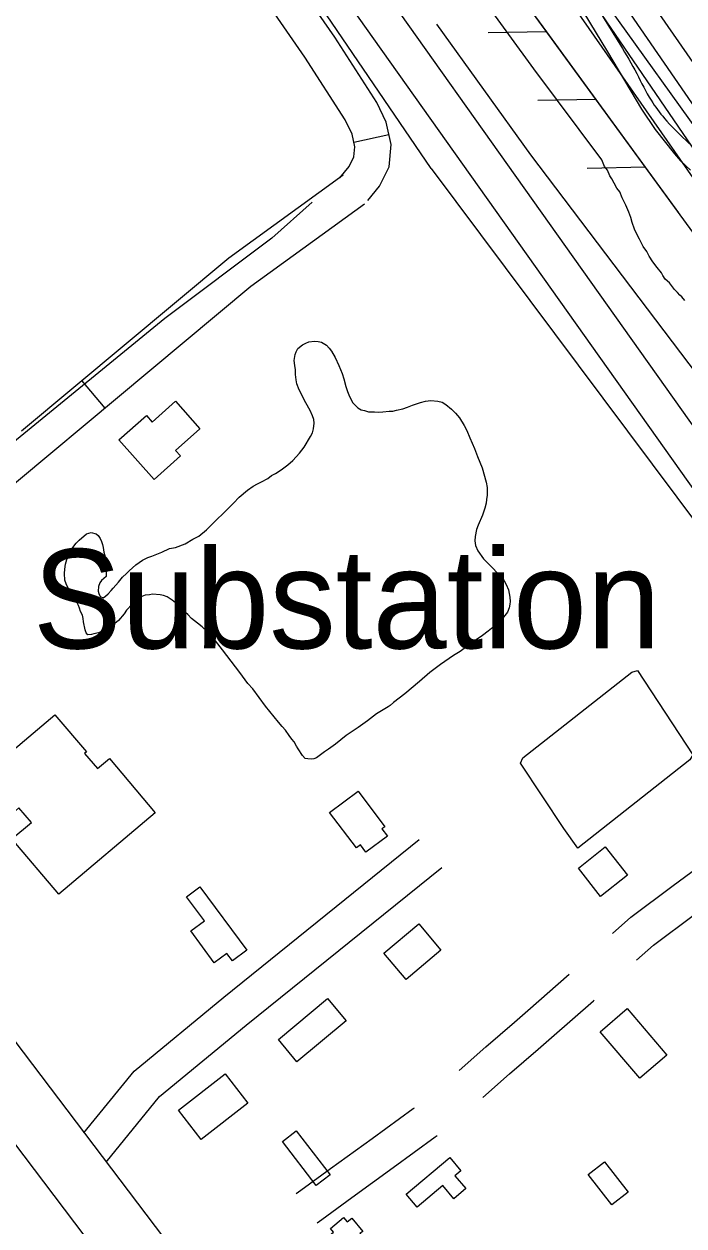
# Model space of a CAD drawing. Extents: x 3892998 to 3931244, y 278583 to 304547.
# Drawn here: x 3910038 to 3910590, y 288917 to 289921 of the extents above; entities that cross this region are included whole.
import ezdxf

# ---------------------------------------------------------------- set-up
doc = ezdxf.new("R2010")
doc.units = 0
for name, color, linetype in [('V-BLDG-OTLN', 7, 'Continuous'), ('V-LEVE-TOET', 7, 'Continuous'), ('V-RIVR-EDGE', 7, 'Continuous'), ('V-ROAD-CNTR', 7, 'Continuous'), ('V-RRAP-FSHR', 7, 'Continuous'), ('V-RRAP-RVMT', 7, 'Continuous'), ('V-SITE-OTLN', 7, 'Continuous'), ('V-SITE-OTLN-IDEN', 7, 'Continuous'), ('V-SITE-VEGE', 7, 'Continuous'), ('V-SURV-LINE', 7, 'Continuous'), ('V-TOPO-DPTH', 7, 'Continuous'), ('V-TOPO-MINR', 7, 'Continuous'), ('V-TOPO-SHOR', 7, 'Continuous'), ('V-TOPO-WATR', 7, 'Continuous')]:
    doc.layers.add(name, color=color, linetype=linetype)

msp = doc.modelspace()

# ---------------------------------------------------------------- linework, layer by layer
at = {"layer": 'V-BLDG-OTLN'}
for points in [[(3910146.9, 289540.7), (3910117.6, 289573.6), (3910140.5, 289594.1), (3910145.3, 289588.6), (3910164.8, 289605.9), (3910185.3, 289582.9), (3910164.9, 289564.8), (3910168.9, 289560.3)], [(3910147.9, 289262.1), (3910067.4, 289194), (3910028.2, 289240.3), (3910044.5, 289254.1), (3910034.1, 289266.3), (3910030.8, 289263.4), (3910017.8, 289278.8), (3910020.5, 289281.1), (3910007.6, 289296.3), (3910064, 289344), (3910090.4, 289312.9), (3910088.9, 289311.7), (3910099.6, 289299), (3910109.6, 289307.4)], [(3910317.3, 289280.1), (3910339.6, 289250.4), (3910337.3, 289248.7), (3910341.9, 289242.7), (3910323.9, 289229.1), (3910319.3, 289235.2), (3910315.9, 289232.7), (3910293.6, 289262.3)], [(3910542.5, 289209.9), (3910520, 289192.3), (3910501.4, 289215.9), (3910523.9, 289233.6)], [(3910185.3, 289200.2), (3910224.3, 289147.2), (3910212.4, 289138.4), (3910207.8, 289144.6), (3910197.2, 289136.8), (3910177.6, 289163.4), (3910189, 289171.8), (3910174.1, 289192)], [(3910386.6, 289147.4), (3910357.5, 289122.8), (3910339, 289144.8), (3910368.1, 289169.4)], [(3910307.3, 289088.4), (3910266.3, 289054.1), (3910250.8, 289072.7), (3910291.9, 289106.9)], [(3910542.1, 289098.6), (3910575.3, 289059.7), (3910552.7, 289040.4), (3910519.5, 289079.2)], [(3910225.3, 289019.4), (3910186.4, 288989.1), (3910167.3, 289013.6), (3910206.2, 289043.9)], [(3910265.7, 288996.4), (3910293.9, 288959.5), (3910282.3, 288950.7), (3910254.1, 288987.6)], [(3910357.4, 288943.4), (3910394, 288974), (3910403.2, 288963), (3910398.3, 288958.9), (3910407.4, 288948.1), (3910397.3, 288939.7), (3910388.2, 288950.6), (3910366.6, 288932.5)], [(3910523.2, 288970.6), (3910542.9, 288945.2), (3910529.2, 288934.6), (3910509.5, 288959.9)], [(3910267.8, 288887.4), (3910296.8, 288911.7), (3910294.2, 288914.7), (3910305.2, 288923.9), (3910308.3, 288920.3), (3910312, 288923.4), (3910321.2, 288912.4), (3910318.9, 288910.5), (3910324, 288904.4), (3910308.3, 288891.2), (3910304.4, 288895.8), (3910278.7, 288874.3)]]:
    msp.add_lwpolyline(points, close=True, dxfattribs=at)
at = {"layer": 'V-LEVE-TOET'}
for points in [[(3910378.5, 289800.4), (3910286.7, 289934.9)], [(3910382.9, 289921.1), (3910461.3, 289811.8)], [(3910461.3, 289811.8), (3910628.4, 289591.3), (3910849.1, 289281.4), (3911091.8, 288969.6), (3911307.9, 288682.5), (3911517.2, 288398.5), (3911743.1, 288106.7), (3911912.1, 287856.3), (3912092.1, 287562.1), (3912212.1, 287362), (3912215.6, 287348.2), (3912217.6, 287327.5), (3912216.8, 287307.9), (3912213.6, 287294.6), (3912212.9, 287280.1), (3912210.5, 287267.1), (3912206.6, 287249.1), (3912208.2, 287229.1), (3912212.5, 287213.8), (3912244.7, 287037.1), (3912258.5, 286987.4), (3912297.4, 286872.3), (3912300, 286844.5)], [(3910378.5, 289800.4), (3910604.3, 289498.3), (3910825.8, 289187.7), (3910970.9, 289000.1), (3911108.1, 288812.8), (3911171.6, 288734.9), (3911181.1, 288722.3), (3911187.7, 288714.9), (3911192.8, 288707.8), (3911200.7, 288696.1), (3911205.8, 288690.6), (3911212, 288681.6), (3911221.8, 288665.5), (3911335.2, 288506.1), (3911542.6, 288236.2), (3911714.3, 288010.6), (3911862.9, 287789.6), (3911999.4, 287569.5), (3912128.4, 287357.1)]]:
    msp.add_lwpolyline(points, dxfattribs=at)
at = {"layer": 'V-RIVR-EDGE'}
msp.add_spline([(3909865.8, 290928.2), (3909862.6, 290923.1), (3909860.7, 290922.6), (3909860.7, 290920.7), (3909870.3, 290905.1), (3909881.9, 290877.9), (3909893.5, 290856.5), (3909906.1, 290843.8), (3909921.6, 290817.6), (3909937.1, 290794.7), (3909948.2, 290777.2), (3909977.7, 290734.4), (3910003.4, 290694.5), (3910040.6, 290645.9), (3910078.4, 290595.3), (3910114.2, 290544.2), (3910151.5, 290493.6), (3910182, 290444.5), (3910200.8, 290413.3), (3910226.9, 290368.6), (3910256.9, 290323.8), (3910278.7, 290289.3), (3910307.7, 290250.4), (3910325.2, 290226.5), (3910363.9, 290167.2), (3910391.4, 290124.9), (3910427.7, 290068.9), (3910449.5, 290036.8), (3910504.2, 289956.6), (3910522.1, 289926.9), (3910550.1, 289879.7), (3910562.2, 289857.4), (3910573.3, 289842.3), (3910610.6, 289806.7), (3910620.8, 289794.1), (3910623.2, 289780), (3910634.8, 289764.4), (3910664.8, 289724), (3910692.4, 289689.5), (3910710.8, 289668.1), (3910721, 289660.3), (3910770.9, 289605.3), (3910782.5, 289588.7), (3910807.7, 289548.4), (3910835.7, 289503.6), (3910862.8, 289470), (3910892.3, 289425.8), (3910920.4, 289383.5), (3910948, 289342.6), (3910968.8, 289304.7), (3911000.2, 289260.9), (3911019.6, 289231.7), (3911055.9, 289191.3), (3911085.5, 289159.7), (3911118.9, 289116.8), (3911139.2, 289091.1), (3911161, 289062.3), (3911184.2, 289025.9), (3911223.4, 288981.6), (3911281.5, 288916.4), (3911313, 288876.9), (3911328.5, 288859.4), (3911346.4, 288837.5), (3911371.6, 288801), (3911404.5, 288751.9), (3911426.7, 288715.4), (3911446.6, 288687.7), (3911479, 288646.8), (3911529.4, 288582.1), (3911550.6, 288552.9), (3911609.2, 288468.3), (3911644.5, 288421.1), (3911677, 288378.8), (3911701.2, 288348.1), (3911741.4, 288303.8), (3911770.9, 288264.9), (3911788.8, 288235.7), (3911834.3, 288164.7), (3911857.5, 288130.2), (3911884.6, 288092.7), (3911915.6, 288045.5), (3911921.9, 288035.8), (3911928.6, 288029.9), (3911972.6, 287945.8), (3911992.9, 287906.4), (3912000.6, 287887), (3912014.7, 287866.5), (3912026.8, 287848.1), (3912066.4, 287785.3), (3912084.8, 287750.8), (3912094.5, 287732.8), (3912094.9, 287726), (3912096.8, 287711.4), (3912096.3, 287704.6), (3912095.4, 287700.3), (3912088.6, 287695.9), (3912085.6, 287696.9), (3912073, 287702.3), (3912062.4, 287706.2), (3912054.1, 287706.2), (3912051.2, 287704.3), (3912049.2, 287697.9), (3912054, 287685.8), (3912068.6, 287663.9), (3912113.1, 287586.6), (3912136.7, 287540.9), (3912153.7, 287513.6), (3912163.8, 287503.9), (3912187.6, 287479.6), (3912207.4, 287453.3), (3912216.1, 287446), (3912226.8, 287436.2), (3912240.8, 287416.8), (3912253.4, 287397.8), (3912271.3, 287366.2), (3912283.9, 287341.4), (3912284.8, 287339), (3912290.2, 287338), (3912303.8, 287344.3), (3912317.4, 287350.5), (3912319.8, 287350.5), (3912322.7, 287350.5), (3912327.6, 287345.7), (3912328.5, 287338.4), (3912335.8, 287321.4), (3912348.4, 287300), (3912369.2, 287275.1), (3912380.3, 287265.4), (3912402.1, 287253.2), (3912416.7, 287243.5), (3912434.2, 287238.1), (3912456.9, 287220), (3912481.6, 287183.6), (3912501.9, 287148.1), (3912512.6, 287124.7), (3912531.4, 287085.8), (3912550.3, 287059.6), (3912569.6, 287034.3), (3912593.3, 286996.8), (3912613.7, 286968.1), (3912632, 286936.5), (3912645.1, 286912.7), (3912660.6, 286888.8), (3912675.1, 286867.4), (3912698.3, 286835.3), (3912720.1, 286784.8), (3912737, 286747.8), (3912742.3, 286740), (3912755.3, 286715.2), (3912761.6, 286696.8), (3912774.1, 286660.3), (3912779.9, 286635.5), (3912793.4, 286585.5), (3912797.2, 286569.4), (3912804, 286543.7), (3912804.4, 286532)], degree=3, dxfattribs=at)
at = {"layer": 'V-ROAD-CNTR'}
for p, q in [((3910313.8, 289822.3), (3910343.1, 289828.8)), ((3910086.4, 289623.2), (3910105.7, 289600.1))]:
    msp.add_line(p, q, dxfattribs=at)
for points in [[(3905312.5, 295227.1), (3905668.2, 294755.9), (3905995.9, 294324.8), (3906423.6, 293758.8), (3906727.8, 293356.2), (3907205.3, 292726.9), (3907628, 292163.3), (3908430.5, 291100.9), (3908883.9, 290504.6), (3909506.7, 289678.1), (3910240.4, 288708.1), (3910610.7, 288220.9)], [(3906034.2, 294352.1), (3906739.3, 293416.8), (3907556.8, 292335.4), (3908052.7, 291678.7), (3908621.7, 290930.2), (3909105, 290293.1), (3909494.8, 289778.2), (3910015.5, 289090.8), (3910630.8, 288278.7)], [(3910325.5, 289773.7), (3910335.2, 289785.7), (3910343.2, 289801.9), (3910344.9, 289820.4), (3910340.8, 289839), (3910333, 289855.6), (3910297.9, 289910.1), (3910262.3, 289961.6)], [(3910302.1, 289792.5), (3910309.8, 289802), (3910313.8, 289810.2), (3910314.6, 289818.5), (3910312.3, 289829.2), (3910306.7, 289841), (3910273, 289893.5), (3910237.8, 289944.4)], [(3910036.2, 289581.3), (3910209.5, 289725.8), (3910305, 289795.2)], [(3909819.8, 289351.7), (3909922, 289446.9), (3910227.9, 289702.2), (3910322.6, 289770.9)], [(3910088.3, 288994.7), (3910130.2, 289046.3), (3910205.1, 289108), (3910368.4, 289239.8)], [(3910530, 289161.3), (3910545.2, 289174.9), (3910580.5, 289201.3), (3910615.4, 289227.1), (3910628.3, 289236.9)], [(3910107, 288970.1), (3910151.6, 289025.1), (3910224, 289084.8), (3910387.2, 289216.4)], [(3910550, 289138.9), (3910564.2, 289151.6), (3910598.4, 289177.2), (3910633.4, 289203.1), (3910646.4, 289213)], [(3910448.1, 289087.3), (3910459.1, 289096.9), (3910493.7, 289127.2), (3910493.8, 289127.3)], [(3910467.8, 289064.7), (3910478.9, 289074.3), (3910514, 289105.1), (3910514.6, 289105.6)], [(3910401.8, 289046.7), (3910424.1, 289066.5), (3910448.1, 289087.3)], [(3910421.6, 289024.2), (3910443.9, 289043.9), (3910467.8, 289064.7)], [(3910265.6, 288943.9), (3910269.5, 288946.7), (3910294.4, 288964.8), (3910329.2, 288990), (3910363.5, 289015), (3910364.4, 289015.7)], [(3910283.3, 288919.6), (3910287.2, 288922.4), (3910312, 288940.6), (3910346.8, 288965.7), (3910381.8, 288991.3), (3910383.3, 288992.5)]]:
    msp.add_lwpolyline(points, dxfattribs=at)
at = {"layer": 'V-RRAP-FSHR'}
for p, q in [((3910475, 289914.6), (3910426.1, 289913.7)), ((3910516.2, 289858), (3910467.4, 289857.1)), ((3910557.5, 289801.5), (3910508.6, 289800.5))]:
    msp.add_line(p, q, dxfattribs=at)
for points in [[(3906808.7, 295088), (3907517.5, 294080), (3908118.6, 293281.7), (3908235.5, 293171.3), (3908399.7, 292987.4), (3908497.6, 292843.4), (3908620.8, 292699.4), (3908781.9, 292472.6), (3908840.2, 292361), (3908947.1, 292209.3), (3909156.9, 291945.8), (3909268, 291726.3), (3910057.1, 290568.3), (3910757.5, 289562.2), (3911229.4, 288921.6), (3911814.1, 288135.2), (3912099.8, 287690.4), (3912357.7, 287495.4), (3912493.3, 287323.3)], [(3911412.6, 288622.2), (3911308, 288752.8), (3911327.8, 288790.6), (3910785.8, 289488.4), (3910445.8, 289954.6), (3910129.3, 290398), (3909798.6, 290866.3), (3909546.9, 291228.9), (3909473.8, 291330.5), (3909414.7, 291394.5), (3909312.2, 291557.4), (3909036.8, 291981.1), (3908774.4, 292360.3)], [(3910475, 289914.6), (3910445.8, 289954.6), (3910433.9, 289971.3)], [(3910516.2, 289858), (3910475, 289914.6)], [(3910557.5, 289801.5), (3910516.2, 289858)], [(3910585.2, 289763.5), (3910557.5, 289801.5)]]:
    msp.add_lwpolyline(points, dxfattribs=at)
at = {"layer": 'V-RRAP-RVMT'}
msp.add_line((3910608.8, 289821.2), (3910527.1, 289935), dxfattribs=at)
at = {"layer": 'V-SITE-OTLN'}
msp.add_lwpolyline([(3910489.1, 289248.9), (3910452.9, 289303.5), (3910454.9, 289308), (3910546.1, 289379.5), (3910550.8, 289381.1), (3910597, 289310.5), (3910594.4, 289306.4), (3910500.8, 289232.5)], close=True, dxfattribs=at)
at = {"layer": 'V-SITE-VEGE'}
for points in [[(3910210.8, 290369), (3910280.2, 290265.4), (3910366.8, 290137.5), (3910460.7, 290005.1), (3910525.6, 289897.9), (3910554.1, 289850), (3910565.5, 289833.1), (3910581.6, 289812.7), (3910586.8, 289806.7)], [(3910590.3, 289690.2), (3910587.8, 289693.3), (3910586, 289694.5), (3910584.2, 289696.9), (3910581.8, 289699.3), (3910577.5, 289704.8), (3910573.8, 289707.9), (3910572, 289710.9), (3910570.8, 289713.3), (3910567.1, 289717.6), (3910563.5, 289722.5), (3910560.4, 289727.3), (3910558.6, 289731), (3910555.6, 289735.2), (3910552.5, 289741.3), (3910550.1, 289745.6), (3910548.3, 289749.8), (3910546.4, 289755.3), (3910545.2, 289759.6), (3910543.4, 289763.8), (3910541, 289769.9), (3910537.9, 289776), (3910536.1, 289780.9), (3910533.6, 289783.9), (3910531.2, 289788.2), (3910529.4, 289791.8), (3910527.6, 289794.2), (3910525.7, 289799.1), (3910523.3, 289802.2), (3910520.9, 289807.6), (3910464.2, 289883.8), (3910422.3, 289941)], [(3910586.8, 289806.7), (3910595.1, 289799.1)], [(3910241.9, 289541.5), (3910245, 289543.8), (3910248.4, 289545.6), (3910253.1, 289548.6), (3910258.6, 289552.9), (3910262.8, 289556.5), (3910268.5, 289562.6), (3910272.4, 289567.5), (3910277.6, 289576.4), (3910279.2, 289579.6), (3910280.1, 289582.9), (3910280.7, 289587.7), (3910280.3, 289590.6), (3910279.3, 289593.8), (3910277.4, 289598.1), (3910273.6, 289604.7), (3910268.1, 289615.5), (3910266.3, 289620.5), (3910265.5, 289623.8), (3910265.1, 289628.2), (3910265.1, 289632.3), (3910264.5, 289635.7), (3910264.1, 289640), (3910264.7, 289644.9), (3910265.5, 289647.3), (3910267.1, 289649.9), (3910270.8, 289653), (3910273.6, 289654.6), (3910276.2, 289655.6), (3910280.9, 289656.2), (3910284.1, 289656), (3910286.8, 289655.2), (3910291, 289652.7), (3910293.1, 289650.3), (3910295.1, 289647.7), (3910298.1, 289642.4), (3910301.4, 289635.7), (3910304, 289629), (3910305.4, 289624.8), (3910307.2, 289618.3)], [(3910307.2, 289618.3), (3910308.6, 289614.2), (3910310.3, 289609.8), (3910313.1, 289604.5), (3910317.1, 289600.5), (3910319.8, 289598.8), (3910322.6, 289598.2), (3910326, 289597.2), (3910331.1, 289597.2), (3910334.6, 289596.8), (3910338, 289597), (3910343.3, 289597.8), (3910346.5, 289597.6), (3910349.4, 289598.4), (3910354.8, 289599.6), (3910358.7, 289600.9), (3910362.9, 289602.7), (3910369.4, 289604.9), (3910373.7, 289606.1), (3910378.1, 289606.7), (3910384, 289606.1), (3910387.6, 289605.1), (3910390.7, 289603.3), (3910395.5, 289599.4), (3910398.6, 289596), (3910402, 289592.1), (3910406.1, 289585.6), (3910408.3, 289581.4), (3910410.7, 289575.5), (3910414.6, 289566.6), (3910417.2, 289559.9), (3910421, 289550.2), (3910424.3, 289538.4), (3910425.1, 289534), (3910425.3, 289527.5), (3910424.7, 289524), (3910424.3, 289520.8), (3910423.3, 289516.7), (3910421.4, 289510.9), (3910417.8, 289502.4), (3910416.4, 289498.7), (3910415.1, 289493), (3910414.9, 289489.2), (3910415.5, 289485.5), (3910417.4, 289480.9), (3910422.2, 289474.2), (3910430.3, 289466.3), (3910433, 289463.1), (3910437.4, 289458.6), (3910439.4, 289456), (3910441.1, 289452.9), (3910442.9, 289448.3), (3910443.7, 289445.4), (3910444.1, 289442.4), (3910444.3, 289438.7), (3910444.1, 289436.5), (3910443.5, 289433.3), (3910442.1, 289429.8), (3910438.8, 289425.6), (3910433.5, 289420.5), (3910430.9, 289418.3), (3910428.9, 289416.1), (3910426, 289413.8), (3910421.2, 289410.2), (3910412.7, 289404.3), (3910402.7, 289397), (3910397.1, 289393.6), (3910386.3, 289386.1), (3910377.4, 289379.2), (3910368.7, 289371.7), (3910356.3, 289361.6), (3910347, 289354.3), (3910344.2, 289351.7), (3910342.4, 289350.7), (3910332.8, 289344.8), (3910325.3, 289338.9), (3910317.4, 289333.4), (3910307.5, 289326.8), (3910298.4, 289319.5), (3910292.7, 289315.2), (3910289.3, 289313), (3910286, 289310.6), (3910282.6, 289308.1), (3910280.3, 289307.3), (3910278.3, 289306.9), (3910275.3, 289307.1), (3910273.2, 289307.5), (3910270.8, 289310), (3910267.2, 289315.6), (3910266, 289317.9), (3910263.9, 289321.5), (3910261.9, 289323.7), (3910259.9, 289326.6), (3910256.6, 289331.2), (3910254, 289334.3), (3910250.8, 289337.7), (3910240, 289351.3), (3910229.3, 289365.7), (3910225.3, 289370.2), (3910218.6, 289379.3), (3910204, 289398.3)], [(3910204, 289398.3), (3910200.2, 289403.4), (3910196.5, 289408.1), (3910191, 289413.9), (3910187.2, 289417.4), (3910183.1, 289420.6), (3910178.1, 289424.5), (3910175, 289427.7), (3910171.8, 289430.6), (3910167.6, 289435), (3910164.7, 289437.4), (3910162.1, 289439.7), (3910157.8, 289442.5), (3910154.8, 289443.7), (3910152, 289444.3), (3910145.7, 289444.7), (3910143.2, 289444.3), (3910139.6, 289443.9), (3910136.8, 289442.9), (3910131.7, 289438.7), (3910128.5, 289436.4), (3910124, 289431.4), (3910122, 289428.4), (3910117.1, 289422.7), (3910112.4, 289419), (3910108.2, 289416.8), (3910105.1, 289414.4), (3910100.5, 289412.4), (3910096.6, 289411.7), (3910094.6, 289411.1), (3910091.6, 289410.9), (3910090.3, 289412.6), (3910089.3, 289415), (3910087.9, 289421.7), (3910087.7, 289424.3), (3910087.1, 289427.1), (3910085.5, 289430.2), (3910084.7, 289433.2), (3910083.9, 289435.3), (3910082.5, 289438.1), (3910081.4, 289439.9), (3910079.2, 289442.5), (3910077.6, 289444.8), (3910073.4, 289453.3), (3910072.5, 289456.5), (3910072.1, 289462), (3910072.3, 289465.7), (3910073, 289469.7), (3910074.6, 289475.6), (3910076.4, 289479), (3910078.2, 289482.7), (3910081.9, 289487.5), (3910084.5, 289490), (3910090.6, 289495.2), (3910094.4, 289496.2), (3910098.5, 289495.2), (3910100.1, 289493.8), (3910101.9, 289491.4), (3910103.1, 289488.7), (3910103.8, 289486.3), (3910104.4, 289483.7), (3910105, 289480), (3910105.8, 289477), (3910107.2, 289470.1), (3910107, 289467.1), (3910107, 289464.8), (3910106.8, 289459.6), (3910102.9, 289456.1), (3910101.5, 289454.1), (3910100.5, 289451.3), (3910100.3, 289447.2), (3910100.7, 289445.2), (3910101.9, 289442.9), (3910104.3, 289441.7), (3910106.4, 289443.1), (3910108.6, 289445), (3910111, 289447.8), (3910112.9, 289449.8), (3910117.1, 289454.9), (3910120.6, 289458.9), (3910124, 289462), (3910126.2, 289464.4), (3910131.7, 289469.3), (3910134.5, 289471.3), (3910137.4, 289473.1), (3910141.8, 289475.5), (3910145.1, 289476.6), (3910153.4, 289480), (3910159.7, 289482.8), (3910164.7, 289483.8), (3910172.8, 289486.7), (3910179.3, 289490.7), (3910184.2, 289493.2), (3910190.7, 289498.4), (3910213.2, 289520.9), (3910218, 289525.8), (3910224.9, 289531.6), (3910229.8, 289534.9), (3910233.2, 289536.9), (3910236.7, 289538.7), (3910241.9, 289541.5)]]:
    msp.add_lwpolyline(points, dxfattribs=at)
at = {"layer": 'V-SURV-LINE'}
for points in [[(3909350, 291341.4), (3910746.5, 289374.8)], [(3910722, 289357.4), (3909325.5, 291324)]]:
    msp.add_lwpolyline(points, dxfattribs=at)
at = {"layer": 'V-TOPO-DPTH'}
msp.add_lwpolyline([(3910555.3, 289949.4), (3910606, 289876.2), (3910673.6, 289778.5), (3910690.5, 289754.1), (3910707.4, 289729.7), (3910724.3, 289705.2), (3910741.1, 289680.8), (3910829.7, 289552.7), (3910891.2, 289464.4), (3910953.1, 289376.4), (3911015.6, 289288.8), (3911078.5, 289201.6), (3911405, 288752.5), (3911692.8, 288405.9), (3911725.3, 288366.3), (3911775.7, 288303.7), (3911782.5, 288295), (3911789.3, 288286.3), (3911795.8, 288277.5), (3911802.2, 288268.6), (3911817.9, 288246.4), (3911925.9, 288126.9)], dxfattribs=at)
at = {"layer": 'V-TOPO-MINR'}
for points in [[(3910470.7, 290037.4), (3910655.7, 289768.5), (3910673, 289743.3), (3910690.4, 289718.1), (3910707.8, 289692.9), (3910725.1, 289667.6), (3910769.3, 289603.5), (3910809, 289546.4), (3910848.9, 289489.5), (3910889.3, 289432.8), (3910930, 289376.4), (3911447.7, 288663.7), (3911733.4, 288338.5), (3911749.7, 288319.2), (3911774.3, 288289.5), (3911778.1, 288284.8), (3911781.8, 288280), (3911785.4, 288275.2), (3911789, 288270.3), (3911801.6, 288252.4)], [(3910555.3, 289949.4), (3910606, 289876.2), (3910673.6, 289778.5), (3910690.5, 289754.1), (3910707.4, 289729.7), (3910724.3, 289705.2), (3910741.1, 289680.8), (3910829.7, 289552.7), (3910891.2, 289464.4), (3910953.1, 289376.4), (3911015.6, 289288.8), (3911078.5, 289201.6), (3911405, 288752.5), (3911692.8, 288405.9), (3911725.3, 288366.3), (3911775.7, 288303.7), (3911782.5, 288295), (3911789.3, 288286.3), (3911795.8, 288277.5), (3911802.2, 288268.6), (3911817.9, 288246.4)]]:
    msp.add_lwpolyline(points, dxfattribs=at)
at = {"layer": 'V-TOPO-SHOR'}
msp.add_lwpolyline([(3910279, 289772.2), (3910245.4, 289742.2), (3910155.8, 289675), (3910028.9, 289571.1)], dxfattribs=at)
at = {"layer": 'V-TOPO-WATR'}
msp.add_lwpolyline([(3910317.9, 290226.1), (3910637.4, 289758.5), (3910655.2, 289732.4), (3910673.1, 289706.3), (3910691, 289680.2), (3910708.9, 289654), (3910727, 289628), (3910745.1, 289602.1), (3910763.5, 289576.3), (3910782, 289550.6), (3911495.9, 288567.5), (3911757.2, 288292.4), (3911760.3, 288289.5), (3911763.3, 288286.5), (3911766.2, 288283.4), (3911769, 288280.2), (3911773, 288275.5), (3911773.7, 288274.6), (3911775.1, 288272.8), (3911775.7, 288271.9), (3911778.8, 288267.6), (3911781, 288264.5), (3911782.9, 288261.5)], dxfattribs=at)

# ---------------------------------------------------------------- texts
at = {"layer": 'V-SITE-OTLN-IDEN'}
msp.add_text('Substation', height=83, dxfattribs=at).set_placement((3910045.7, 289399.4))

doc.saveas('drawing.dxf')
